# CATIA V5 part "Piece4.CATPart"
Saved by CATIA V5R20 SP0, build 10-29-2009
Part number: Piece4
Bounding box of the stored display mesh (mm): x 0 to 20, y -16.358 to 52.685, z -81.982 to 28.168
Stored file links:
  C:\Users\ASUS\Desktop\Think Motion IAO\Piece4.CATPart
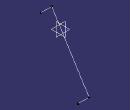
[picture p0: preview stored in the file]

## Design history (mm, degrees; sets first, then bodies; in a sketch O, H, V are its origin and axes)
Body1 (main body)
  Point1 "Point.D": stored without definition
  Line1: type PtDir, RefPoint Point1, Direction yz-plane, Start 0, End 20
  Point2 "Point.E": stored without definition
  Line2: type PtDir, RefPoint Point2, Direction yz-plane, Start 0, End 20
  Point3 "Point.D": stored without definition
  Point4 "Point.E": stored without definition
  Line3: type PtPt, FirstPoint Point3, SecondPoint Point4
